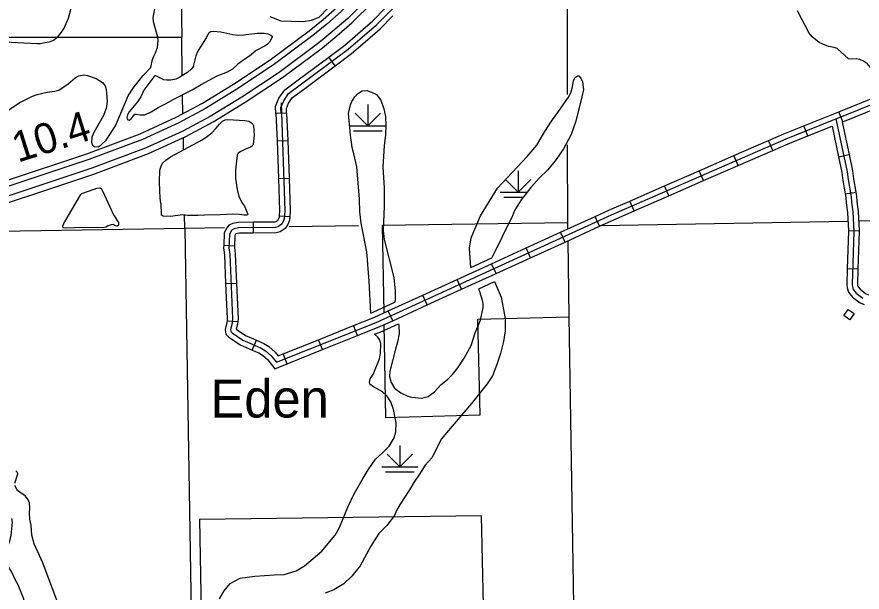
# Model space of a CAD drawing. Extents: x 1084508 to 1142749, y 1057638 to 1093403.
# Drawn here: x 1093716 to 1097414, y 1070508 to 1073024 of the extents above; entities that cross this region are included whole.
import ezdxf

# ---------------------------------------------------------------- set-up
doc = ezdxf.new("R2010")
doc.units = 0
for name, color, linetype in [('Level 19', 7, 'Continuous'), ('Level 24', 7, 'Continuous'), ('Level 32', 7, 'Continuous'), ('Level 35', 7, 'Continuous'), ('Level 4', 7, 'Continuous'), ('Level 44', 7, 'Continuous'), ('Level 45', 7, 'Continuous'), ('Level 47', 7, 'Continuous'), ('Level 48', 7, 'Continuous'), ('Level 5', 7, 'Continuous'), ('Level 56', 7, 'Continuous'), ('Level 7', 7, 'Continuous')]:
    doc.layers.add(name, color=color, linetype=linetype)

msp = doc.modelspace()

# ---------------------------------------------------------------- linework, layer by layer
at = {"layer": 'Level 19'}
for points in [[(1094824.2, 1072836.3), (1094995.1, 1072963.6), (1095055.5, 1073012.7), (1095117.5, 1073066.5), (1095486.3, 1073431.5), (1096480.2, 1074407.3), (1097000.3, 1074928.2)], [(1097019, 1074909.2), (1096499, 1074388.4), (1095505.1, 1073412.5), (1095135.6, 1073046.9), (1095072.6, 1072992.2), (1095011.5, 1072942.5), (1094839.5, 1072814.5)], [(1097047.6, 1074880.1), (1096527.8, 1074359.4), (1095533.7, 1073383.4), (1095163.4, 1073016.9), (1095098.9, 1072961), (1095036.6, 1072910.3), (1094863, 1072781.1)], [(1094878.4, 1072759.3), (1095052.9, 1072889.2), (1095116.1, 1072940.5), (1095181.5, 1072997.4), (1095552.4, 1073364.4), (1096546.5, 1074340.5), (1097066.3, 1074861.1)], [(1092224.5, 1071828.5), (1094022, 1072425.4), (1094255.5, 1072513), (1094412.9, 1072585.2), (1094527.8, 1072646.8), (1094664.6, 1072730.4), (1094824.2, 1072836.3)], [(1094839.5, 1072814.5), (1094678.9, 1072707.9), (1094541.1, 1072623.6), (1094424.8, 1072561.3), (1094265.8, 1072488.3), (1094030.9, 1072400.2), (1092232.9, 1071803.1)], [(1094863, 1072781.1), (1094700.8, 1072673.4), (1094561.4, 1072588.2), (1094443, 1072524.7), (1094281.4, 1072450.7), (1094044.5, 1072361.7), (1092245.7, 1071764.4)], [(1092254, 1071739), (1094053.4, 1072336.6), (1094291.7, 1072426), (1094454.8, 1072500.8), (1094574.7, 1072565.1), (1094715.2, 1072650.9), (1094878.4, 1072759.3)]]:
    msp.add_lwpolyline(points, dxfattribs=at)
at = {"layer": 'Level 32'}
for p, q in [((1097329.7, 1072565.5), (1097312.2, 1072609.2)), ((1097175.9, 1072503.8), (1097158.4, 1072547.5)), ((1094854.3, 1072482.3), (1094901.4, 1072483.9)), ((1097023.6, 1072440.3), (1097004.7, 1072483.5)), ((1096871.7, 1072374.1), (1096852.8, 1072417.2)), ((1097311, 1072411.7), (1097357, 1072421.6)), ((1096719.8, 1072307.8), (1096700.9, 1072350.9)), ((1094860.1, 1072316.7), (1094907.2, 1072318.3)), ((1096567.9, 1072241.5), (1096549, 1072284.7)), ((1097339.6, 1072249.5), (1097386, 1072257.6)), ((1096416, 1072175.2), (1096397.1, 1072218.4)), ((1094863.5, 1072153.5), (1094910.5, 1072150.3)), ((1096264.9, 1072108.1), (1096245.4, 1072150.9)), ((1094749.9, 1072125.6), (1094750.5, 1072078.5)), ((1096114.1, 1072039.3), (1096094.6, 1072082.1)), ((1097353.8, 1072087.6), (1097400.8, 1072089.7)), ((1094621.1, 1072025.3), (1094668.1, 1072023)), ((1095963.3, 1071970.5), (1095943.8, 1072013.3)), ((1095812.6, 1071901.7), (1095793, 1071944.5)), ((1097348.6, 1071923.8), (1097395.6, 1071922.3)), ((1094629.6, 1071857.7), (1094676.7, 1071859.8)), ((1095661.8, 1071832.9), (1095642.2, 1071875.7)), ((1095511, 1071764.1), (1095491.5, 1071806.9)), ((1095360.2, 1071695.3), (1095340.7, 1071738.1)), ((1094635.8, 1071695.2), (1094682.7, 1071691.3)), ((1095206.7, 1071630.2), (1095189.1, 1071673.9)), ((1094745.8, 1071566.9), (1094765, 1071609.9)), ((1095052.8, 1071568.6), (1095035.3, 1071612.3)), ((1094899, 1071506.9), (1094881.5, 1071550.7))]:
    msp.add_line(p, q, dxfattribs=at)
for points in [[(1097081, 1072491.1), (1098396, 1073018.9)], [(1097312.2, 1072609.2), (1097466, 1072671)], [(1094872, 1072648.7), (1094888.6, 1072176.2), (1094886.2, 1072140.6), (1094880.2, 1072126.8), (1094873.4, 1072115.8), (1094858.4, 1072106.1), (1094847.6, 1072103.2), (1094686.5, 1072101.3), (1094667.5, 1072097.4), (1094657.7, 1072093.2), (1094653.2, 1072087.7), (1094646.9, 1072072.4), (1094644.1, 1072014.4), (1094647.4, 1071984.6), (1094660.2, 1071704.3), (1094658.4, 1071683.8), (1094651.3, 1071656.5), (1094652.9, 1071647.7), (1094657.5, 1071642.9), (1094705.2, 1071610.5), (1094742.1, 1071594.3), (1094785.5, 1071575), (1094804.5, 1071563.4), (1094829.4, 1071541.8), (1094851.8, 1071513.4), (1095287.7, 1071688.1), (1096317.9, 1072158.1), (1097081, 1072491.1)], [(1094848.5, 1072601.5), (1094854.3, 1072482.3)], [(1094895.6, 1072602.2), (1094901.4, 1072483.9)], [(1097158.4, 1072547.5), (1097312.2, 1072609.2)], [(1097329.7, 1072565.5), (1097483.5, 1072627.3)], [(1097299.3, 1072578.7), (1097349, 1072346.8), (1097352.6, 1072312.1), (1097365.8, 1072236.3), (1097367.5, 1072213.4), (1097373.7, 1072171.2), (1097377.4, 1072085.9), (1097369.8, 1071854.3), (1097371.1, 1071844), (1097375.3, 1071831.9), (1097388, 1071815.7), (1097417, 1071794.1)], [(1097326.4, 1072564.2), (1097329.7, 1072565.5)], [(1097326.4, 1072564.2), (1097357, 1072421.6)], [(1097004.7, 1072483.5), (1097071.9, 1072512.8), (1097158.4, 1072547.5)], [(1097175.9, 1072503.8), (1097282.1, 1072546.4)], [(1097282.1, 1072546.4), (1097311, 1072411.7)], [(1094901.4, 1072483.9), (1094907.2, 1072318.3)], [(1096852.8, 1072417.2), (1097004.7, 1072483.5)], [(1097023.6, 1072440.3), (1097090.1, 1072469.4), (1097175.9, 1072503.8)], [(1094854.3, 1072482.3), (1094860.1, 1072316.7)], [(1096700.9, 1072350.9), (1096852.8, 1072417.2)], [(1096871.7, 1072374.1), (1097023.6, 1072440.3)], [(1097311, 1072411.7), (1097325.7, 1072343.1), (1097329.3, 1072308.8), (1097339.6, 1072249.5)], [(1097357, 1072421.6), (1097372.2, 1072350.5), (1097376, 1072315.4), (1097386, 1072257.6)], [(1096719.8, 1072307.8), (1096871.7, 1072374.1)], [(1096549, 1072284.7), (1096700.9, 1072350.9)], [(1094860.1, 1072316.7), (1094865.1, 1072176.6), (1094863.5, 1072153.5)], [(1094907.2, 1072318.3), (1094912.2, 1072175.8), (1094910.5, 1072150.3)], [(1096567.9, 1072241.5), (1096719.8, 1072307.8)], [(1096397.1, 1072218.4), (1096549, 1072284.7)], [(1096416, 1072175.2), (1096567.9, 1072241.5)], [(1097339.6, 1072249.5), (1097342.4, 1072233.4), (1097344.1, 1072210.8), (1097350.2, 1072169), (1097353.8, 1072087.6)], [(1097386, 1072257.6), (1097389.2, 1072239.2), (1097391, 1072216), (1097397.1, 1072173.4), (1097400.8, 1072089.7)], [(1096245.4, 1072150.9), (1096308.3, 1072179.6), (1096397.1, 1072218.4)], [(1094863.5, 1072153.5), (1094863, 1072146.3), (1094859.3, 1072137.8), (1094856.2, 1072132.7), (1094848.7, 1072127.9), (1094844.3, 1072126.7), (1094749.9, 1072125.6)], [(1094910.5, 1072150.3), (1094909.5, 1072134.9), (1094901.1, 1072115.8), (1094890.6, 1072099), (1094868.1, 1072084.4), (1094850.8, 1072079.7), (1094750.5, 1072078.5)], [(1096094.6, 1072082.1), (1096245.4, 1072150.9)], [(1096264.9, 1072108.1), (1096327.5, 1072136.6), (1096416, 1072175.2)], [(1094749.9, 1072125.6), (1094684, 1072124.8), (1094660.5, 1072120), (1094643.1, 1072112.6), (1094632.7, 1072099.9), (1094623.6, 1072077.5), (1094621.1, 1072025.3)], [(1094750.5, 1072078.5), (1094689, 1072077.8), (1094674.5, 1072074.8), (1094673.1, 1072074.2), (1094670.2, 1072067.2), (1094668.1, 1072023)], [(1095943.8, 1072013.3), (1096094.6, 1072082.1)], [(1096114.1, 1072039.3), (1096264.9, 1072108.1)], [(1097353.8, 1072087.6), (1097353.9, 1072085.8), (1097348.6, 1071923.8)], [(1097400.8, 1072089.7), (1097401, 1072086.1), (1097395.6, 1071922.3)], [(1095963.3, 1071970.5), (1096114.1, 1072039.3)], [(1094621.1, 1072025.3), (1094620.5, 1072013.6), (1094624, 1071982.8), (1094629.6, 1071857.7)], [(1094668.1, 1072023), (1094667.7, 1072015.1), (1094670.9, 1071986.5), (1094676.7, 1071859.8)], [(1095793, 1071944.5), (1095943.8, 1072013.3)], [(1095812.6, 1071901.7), (1095963.3, 1071970.5)], [(1095642.2, 1071875.7), (1095793, 1071944.5)], [(1095661.8, 1071832.9), (1095812.6, 1071901.7)], [(1097348.6, 1071923.8), (1097346.2, 1071853.2), (1097348, 1071838.6), (1097354.3, 1071820.4), (1097371.5, 1071798.7), (1097404.9, 1071773.7), (1097422.5, 1071765.5)], [(1097395.6, 1071922.3), (1097393.4, 1071855.4), (1097394.2, 1071849.3), (1097396.2, 1071843.3), (1097404.6, 1071832.7), (1097429.1, 1071814.4), (1097442.3, 1071808.2)], [(1094629.6, 1071857.7), (1094636.6, 1071704.8), (1094635.8, 1071695.2)], [(1094676.7, 1071859.8), (1094683.7, 1071703.9), (1094682.7, 1071691.3)], [(1095491.5, 1071806.9), (1095642.2, 1071875.7)], [(1095511, 1071764.1), (1095661.8, 1071832.9)], [(1095340.7, 1071738.1), (1095491.5, 1071806.9)], [(1095360.2, 1071695.3), (1095511, 1071764.1)], [(1095189.1, 1071673.9), (1095278.4, 1071709.7), (1095340.7, 1071738.1)], [(1094635.8, 1071695.2), (1094635.1, 1071687.8), (1094627.3, 1071657.4), (1094631, 1071636.7), (1094642.1, 1071624.9), (1094693.7, 1071589.8), (1094732.6, 1071572.8), (1094745.8, 1071566.9)], [(1094682.7, 1071691.3), (1094681.7, 1071679.8), (1094676.2, 1071658.6), (1094716.6, 1071631.2), (1094751.7, 1071615.9), (1094765, 1071609.9)], [(1095035.3, 1071612.3), (1095189.1, 1071673.9)], [(1095206.7, 1071630.2), (1095297, 1071666.4), (1095360.2, 1071695.3)], [(1094765, 1071609.9), (1094796.5, 1071595.9), (1094818.4, 1071582.5), (1094846.5, 1071558.1), (1094859.4, 1071541.8), (1094881.5, 1071550.7)], [(1094881.5, 1071550.7), (1095035.3, 1071612.3)], [(1095052.8, 1071568.6), (1095206.7, 1071630.2)], [(1094745.8, 1071566.9), (1094774.6, 1071554.1), (1094790.5, 1071544.4), (1094812.3, 1071525.5), (1094844.3, 1071485), (1094899, 1071506.9)], [(1094899, 1071506.9), (1095052.8, 1071568.6)]]:
    msp.add_lwpolyline(points, dxfattribs=at)
at = {"layer": 'Level 35'}
for points in [[(1093604.7, 1072917.1), (1093803, 1072907.1), (1093818.7, 1072907.7), (1093863, 1072915.9), (1093876.2, 1072922.4), (1093894.8, 1072937.1), (1093909, 1072952.2), (1093923.7, 1072974.6), (1093942, 1073018.2), (1093969, 1073117)], [(1097226.2, 1072912.2), (1097194.7, 1072936.4), (1097182.7, 1072952.2), (1097131.7, 1073050)], [(1094488.4, 1072807.6), (1094500.9, 1072853.7), (1094506.8, 1072870.4), (1094543.4, 1072928.7), (1094557.3, 1072955.7), (1094564.7, 1072960.1), (1094574.4, 1072960.8), (1094607.9, 1072958.1), (1094661.1, 1072947.5), (1094685.8, 1072944.7), (1094708.1, 1072945.3), (1094767.2, 1072953.5), (1094797.4, 1072953.2), (1094814.5, 1072949.8), (1094823.8, 1072945.4), (1094832.6, 1072939.5), (1094833.4, 1072935.4), (1094821.1, 1072913.2), (1094813, 1072904.6), (1094802.9, 1072897.6), (1094763.8, 1072877.1), (1094733.4, 1072851.8), (1094712.9, 1072838.7), (1094682.7, 1072816.5)], [(1097532.1, 1072697.5), (1097501.6, 1072718.1), (1097485.7, 1072734.5), (1097472.4, 1072755.1), (1097450.4, 1072803), (1097436.7, 1072818.9), (1097420.4, 1072829.9), (1097403.2, 1072837.2), (1097388.3, 1072840.8), (1097368.3, 1072838.5), (1097354.4, 1072840.9), (1097304.9, 1072886), (1097291.9, 1072889.9), (1097266, 1072894.1), (1097242.5, 1072904.2), (1097226.2, 1072912.2)], [(1094488.4, 1072807.6), (1094479, 1072795.4), (1094464.1, 1072782.6), (1094429.1, 1072760.1), (1094412.4, 1072752.3), (1094389.7, 1072747.8), (1094372.8, 1072747.2), (1094359.6, 1072749.3), (1094347.2, 1072754.3), (1094338.6, 1072759.6), (1094324.2, 1072766.4), (1094320.5, 1072765.7), (1094315.3, 1072761.1), (1094272.1, 1072703.1), (1094258.9, 1072674.3), (1094244.5, 1072652.5), (1094207.7, 1072608.8), (1094200.9, 1072595.7), (1094197.2, 1072584.6), (1094198.1, 1072577.4), (1094201.9, 1072574.4), (1094207.6, 1072572.7), (1094216.8, 1072578), (1094229.7, 1072596), (1094233.7, 1072598.4), (1094239.4, 1072599.2), (1094255.1, 1072595.9), (1094275.5, 1072595), (1094303.9, 1072608.5), (1094334, 1072627.7), (1094367, 1072643.3), (1094400.2, 1072663.2), (1094483.2, 1072705.3), (1094522.2, 1072728.6), (1094593.1, 1072766.7), (1094637.4, 1072783.9), (1094660.8, 1072796.9), (1094682.7, 1072816.5)], [(1094345.6, 1072208.7), (1094343.3, 1072231.2), (1094340.7, 1072301), (1094341.5, 1072354.1), (1094347, 1072371), (1094353.7, 1072384.1), (1094368, 1072397.8), (1094387.9, 1072411.9), (1094526.9, 1072486.6), (1094550.8, 1072502.5), (1094569.1, 1072517.2), (1094587.3, 1072536.1), (1094602.7, 1072555.1), (1094615.2, 1072567.2), (1094627.8, 1072573.9), (1094639.7, 1072575.2), (1094712.8, 1072571), (1094730.5, 1072567.5), (1094742.3, 1072561.3), (1094748.8, 1072554.9), (1094752.1, 1072546.8), (1094754.4, 1072507.3), (1094750.6, 1072467.5), (1094745.6, 1072459.2), (1094738.2, 1072453.6), (1094713.8, 1072444.3), (1094696.5, 1072435.6), (1094684.2, 1072427.3), (1094680.1, 1072419.9), (1094673.4, 1072355.3), (1094672.1, 1072317.2), (1094679.6, 1072269), (1094686.8, 1072238.1), (1094702.8, 1072208.4), (1094712, 1072196.5), (1094726.1, 1072161.1)], [(1093991.4, 1072240.5), (1093996.2, 1072247.9), (1094001.1, 1072251.8), (1094054.3, 1072271.1), (1094065.8, 1072275), (1094079.6, 1072276.4), (1094085, 1072273.1), (1094090.6, 1072263.8), (1094139.1, 1072158.5), (1094160.2, 1072125.3), (1094160.6, 1072113.3), (1094154.8, 1072108.4), (1094146.6, 1072110.4), (1094137, 1072115.7), (1094128.3, 1072115.1), (1094113.4, 1072109), (1094106.1, 1072104), (1094092.4, 1072102), (1094009.9, 1072103.4), (1093927, 1072099.4), (1093920.6, 1072101.7), (1093916.8, 1072105), (1093916.9, 1072110.4), (1093921.6, 1072120.6)], [(1093921.6, 1072120.6), (1093991.4, 1072240.5)], [(1094345.6, 1072208.7), (1094347.5, 1072158.1)], [(1094726.1, 1072161.1), (1094725.3, 1072158.9), (1094721, 1072156.6), (1094710.4, 1072156.2), (1094689.6, 1072159.9), (1094661, 1072161.2), (1094606.3, 1072157.8), (1094536.7, 1072157.4), (1094508.6, 1072155.6), (1094463.8, 1072155.4), (1094440.2, 1072158.4), (1094388.7, 1072150.7), (1094356.7, 1072152.2), (1094348.4, 1072156.6), (1094347.5, 1072158.1)], [(1093882.6, 1070173.3), (1093855.7, 1070200.1), (1093834.3, 1070234), (1093808.9, 1070282.9), (1093795.1, 1070312.3), (1093764.7, 1070399.9), (1093754.1, 1070447.7), (1093744.9, 1070481.4), (1093721.3, 1070540.3), (1093710, 1070560.4), (1093694.2, 1070595.7), (1093676.6, 1070625.3), (1093669.4, 1070646.5), (1093666.6, 1070664.3), (1093668.4, 1070685.1), (1093673.2, 1070701.3), (1093684.3, 1070728.7), (1093691.8, 1070756), (1093697.5, 1070814.4), (1093694.2, 1070830)]]:
    msp.add_lwpolyline(points, dxfattribs=at)
at = {"layer": 'Level 4'}
for points in [[(1096125, 1072684.4), (1096122.9, 1073763)], [(1096126, 1072123.5), (1096125.4, 1072463.9)], [(1096181.8, 1068846.7), (1096153.4, 1070453), (1096132.8, 1071712.6)]]:
    msp.add_lwpolyline(points, dxfattribs=at)
at = {"layer": 'Level 44'}
for p, q in [((1095251, 1072641.1), (1095251, 1072546.9)), ((1095251, 1072546.9), (1095195.5, 1072602.4)), ((1095251, 1072546.9), (1095306.4, 1072602.4)), ((1095172.5, 1072546.9), (1095329.4, 1072546.9)), ((1095188.2, 1072525.5), (1095313.7, 1072525.5)), ((1095909.5, 1072351.1), (1095909.5, 1072256.9)), ((1095909.5, 1072256.9), (1095854, 1072312.4)), ((1095909.5, 1072256.9), (1095965, 1072312.4)), ((1095831.1, 1072256.9), (1095947.7, 1072256.9)), ((1095846.8, 1072235.6), (1095930.7, 1072235.6)), ((1095391.3, 1071150), (1095391.3, 1071055.9)), ((1095391.3, 1071055.9), (1095335.8, 1071111.4)), ((1095391.3, 1071055.9), (1095446.8, 1071111.4)), ((1095312.8, 1071055.9), (1095469.8, 1071055.9)), ((1095328.5, 1071034.5), (1095454.1, 1071034.5))]:
    msp.add_line(p, q, dxfattribs=at)
at = {"layer": 'Level 45'}
for p, q in [((1095108.4, 1072810.2), (1095080.3, 1072847.9)), ((1094895.6, 1072602.2), (1094848.5, 1072601.5))]:
    msp.add_line(p, q, dxfattribs=at)
for points in [[(1094872, 1072601.8), (1094871.6, 1072628.2), (1094883.4, 1072657.5), (1094905.2, 1072688.2), (1095165.8, 1072882.2), (1095289, 1072989), (1095408.9, 1073110.3), (1096240.7, 1073920.5)], [(1095208.3, 1072950.2), (1095272.9, 1073006.2), (1095328.1, 1073062)], [(1095239.2, 1072914.7), (1095305.1, 1072971.8), (1095361.6, 1073028.9)], [(1095080.3, 1072847.9), (1095151, 1072900.6), (1095208.3, 1072950.2)], [(1095108.4, 1072810.2), (1095180.5, 1072863.8), (1095239.2, 1072914.7)], [(1094947.4, 1072749), (1095080.3, 1072847.9)], [(1094975.5, 1072711.2), (1095108.4, 1072810.2)], [(1094848.5, 1072601.5), (1094848, 1072632.6), (1094862.6, 1072668.8), (1094888.1, 1072704.8), (1094947.4, 1072749)], [(1094895.6, 1072602.2), (1094895.3, 1072623.8), (1094904.3, 1072646.1), (1094922.2, 1072671.5), (1094975.5, 1072711.2)]]:
    msp.add_lwpolyline(points, dxfattribs=at)
at = {"layer": 'Level 47'}
for points in [[(1094302.1, 1072802.8), (1094309.1, 1072837.8), (1094314.8, 1072851.9), (1094323.3, 1072867.1), (1094332.1, 1072890.5), (1094334.6, 1072920.5), (1094333, 1072935.6), (1094314.7, 1073002.9), (1094312.4, 1073021.1), (1094322.1, 1073074.5)], [(1094823, 1073026.1), (1094871.2, 1073007.3), (1094918.2, 1073004.6), (1094969.2, 1073004.5), (1095004.8, 1073009.5), (1095039.1, 1073023.2), (1095078.3, 1073063.3)], [(1093648.7, 1072596.2), (1093726.4, 1072647.5), (1093784.7, 1072676.7), (1093804.8, 1072684.3), (1093849.3, 1072694.2), (1093882.4, 1072698.5), (1093899.4, 1072704.1), (1093940.2, 1072730.9), (1093971, 1072757.7), (1093988, 1072766.7), (1094008.9, 1072770.5), (1094024.9, 1072767.3), (1094063.6, 1072755), (1094091.1, 1072736.8), (1094103.2, 1072722.4), (1094107.1, 1072705.8), (1094111.9, 1072655.7), (1094107, 1072623.1), (1094093.6, 1072589.4), (1094052.4, 1072518.2), (1094043.6, 1072497.8), (1094042.1, 1072475.8), (1094046.6, 1072462.7), (1094055.3, 1072456.4), (1094071.3, 1072456), (1094085.4, 1072464), (1094106.4, 1072484.8), (1094147.9, 1072548.1), (1094202.6, 1072679.4), (1094225.1, 1072712.5), (1094266.9, 1072765.5), (1094302.1, 1072802.8)], [(1095702.3, 1071927.7), (1095696.2, 1072013), (1095703.3, 1072057.9), (1095743.7, 1072153.9), (1095818.8, 1072274.6), (1095947.9, 1072413.4), (1095991.4, 1072463.2), (1096026.1, 1072522.8), (1096055.7, 1072568.1), (1096083.3, 1072605.2), (1096132.1, 1072676.6), (1096140.9, 1072695.7), (1096147.1, 1072718.3), (1096151.6, 1072745.1), (1096158.3, 1072758.3), (1096168.1, 1072766.4), (1096174.1, 1072765.7), (1096182.9, 1072755.9), (1096190.3, 1072739.8), (1096194.8, 1072706.9), (1096188.3, 1072674.3), (1096161.6, 1072567.5), (1096141.6, 1072509.9), (1096106.9, 1072446.2), (1096075.5, 1072399.6), (1096038.4, 1072355), (1096001, 1072318.9), (1095964.4, 1072278.1), (1095921.7, 1072224.2), (1095893.4, 1072177.3), (1095884.4, 1072154.1), (1095794.4, 1071969.7)], [(1095264.6, 1071728.7), (1095258.1, 1071867.6), (1095246.7, 1071997), (1095221.7, 1072121.7), (1095217, 1072171.2), (1095214.9, 1072226.5), (1095203.5, 1072368.2), (1095190.7, 1072425.7), (1095182.9, 1072453.1), (1095175.6, 1072506), (1095167.5, 1072601.6), (1095175.7, 1072639), (1095182.1, 1072654.6), (1095194.9, 1072674.8), (1095206.1, 1072687.4), (1095226.3, 1072701), (1095247, 1072702), (1095267.9, 1072695.4), (1095288.9, 1072684.2), (1095308.5, 1072660.3), (1095322, 1072621.4), (1095328.4, 1072588.3), (1095330.5, 1072550.7), (1095328.8, 1072507.2), (1095323.7, 1072460.8), (1095317, 1072366.3), (1095323.7, 1072275.9), (1095323.7, 1072196.4), (1095319.3, 1072090.3), (1095322.7, 1072050.8), (1095366, 1071884.6), (1095371.4, 1071824.4), (1095371.6, 1071789.2), (1095370.3, 1071776.2)], [(1095702.3, 1071927.7), (1095794.4, 1071969.7)], [(1095806.1, 1071866.8), (1095834.7, 1071798.4), (1095852.5, 1071704.3), (1095852.3, 1071651.5), (1095845.4, 1071604.4), (1095831.4, 1071552.1), (1095815.4, 1071503.2), (1095796.6, 1071453.5), (1095773.6, 1071419.7), (1095704.6, 1071333.2), (1095595, 1071204.2), (1095574.5, 1071178.3), (1095551.4, 1071137), (1095532.6, 1071097.7), (1095502, 1071063.4), (1095478.2, 1071023.9), (1095452.8, 1070987.9), (1095433.8, 1070954.9), (1095392.5, 1070892.8), (1095376.8, 1070865), (1095368.1, 1070843.9), (1095335, 1070800.1), (1095299.5, 1070764), (1095264.3, 1070709.4), (1095218.5, 1070623.3), (1095181.4, 1070577.5), (1095146.1, 1070544.2), (1095102.5, 1070518), (1095065.3, 1070503.6)], [(1095736.5, 1071835.1), (1095806.1, 1071866.8)], [(1095621.5, 1071460), (1095644.8, 1071488.8), (1095673.1, 1071531.8), (1095703, 1071586.3), (1095721.6, 1071642.8), (1095744.9, 1071697.1), (1095756.3, 1071753.4), (1095755.4, 1071771), (1095752, 1071789.4), (1095736.5, 1071835.1)], [(1095264.6, 1071728.7), (1095278, 1071734.1), (1095370.3, 1071776.2)], [(1095281.3, 1071635.8), (1095306, 1071645.7), (1095385.7, 1071682.1)], [(1095385.7, 1071682.1), (1095387.8, 1071674), (1095388.9, 1071639.8), (1095381.6, 1071602.1), (1095372.6, 1071571.3), (1095347.8, 1071474.3), (1095346.7, 1071450.7), (1095353.2, 1071424.5), (1095368.7, 1071399.9), (1095396, 1071380), (1095426.5, 1071365.9), (1095444.2, 1071361.1), (1095485.7, 1071356.8), (1095515.9, 1071363.8), (1095543.4, 1071384.5), (1095572.8, 1071416.6), (1095600.6, 1071438.6), (1095621.5, 1071460)], [(1095226.7, 1071000), (1095252.9, 1071043.3), (1095285, 1071089.3), (1095316.9, 1071119), (1095344.5, 1071147.2), (1095366.9, 1071183.5), (1095373.9, 1071209.5), (1095375.7, 1071249.2), (1095364.5, 1071306.6), (1095352.5, 1071339.9), (1095334, 1071367.3), (1095316, 1071383.7), (1095276.7, 1071406), (1095261, 1071417.4), (1095259.4, 1071426.1), (1095261.5, 1071441), (1095274.7, 1071459.3), (1095303.2, 1071528.5), (1095307.1, 1071551.6), (1095307.9, 1071595), (1095302.6, 1071612.8), (1095294.8, 1071623.8), (1095281.3, 1071635.8)], [(1093706.8, 1070984.8), (1093720.2, 1071025.4), (1093719, 1071031.7), (1093711.3, 1071038)], [(1093900.8, 1070445.9), (1093830.4, 1070636.3), (1093792.7, 1070719.4), (1093781.4, 1070756.7), (1093778.8, 1070800.7), (1093773.6, 1070826.9), (1093771.5, 1070853.3), (1093772.9, 1070877.2), (1093771, 1070898.2), (1093765.5, 1070911.9), (1093753.4, 1070928.4), (1093719.4, 1070953.1), (1093707.7, 1070974.1)], [(1094602.6, 1070479), (1094622.8, 1070514.2), (1094649.4, 1070545.3), (1094692.8, 1070569.6), (1094757.4, 1070577.4), (1094841.8, 1070584.3), (1094886.3, 1070584.8), (1094938.1, 1070601.6), (1094974, 1070623.2), (1095049.7, 1070687.6), (1095086, 1070729.4), (1095108.2, 1070757.4), (1095127.9, 1070790.5), (1095163.6, 1070879.4), (1095192.4, 1070938.2), (1095226.7, 1071000)]]:
    msp.add_lwpolyline(points, dxfattribs=at)
at = {"layer": 'Level 5'}
for points in [[(1094440, 1072770.9), (1094437.4, 1072935.1)], [(1094442.8, 1072601.2), (1094441.5, 1072679.1)], [(1094445.3, 1072446.1), (1094444.5, 1072496.1)], [(1094451, 1072098.9), (1094450, 1072157.1)], [(1097352, 1072129.1), (1096268.7, 1072109.8)], [(1097893, 1072138.7), (1097399.1, 1072129.9)], [(1094624.7, 1072101.5), (1094451, 1072098.9), (1093280.9, 1072080)], [(1094451, 1072098.9), (1094478.5, 1070419.9), (1094480, 1070334.9)], [(1095210.8, 1072110.1), (1094907.5, 1072105.6)]]:
    msp.add_lwpolyline(points, dxfattribs=at)
at = {"layer": 'Level 56'}
msp.add_lwpolyline([(1097379.2, 1071726.1), (1097360.7, 1071699.2), (1097333.7, 1071717.7), (1097352.2, 1071744.6)], close=True, dxfattribs=at)
at = {"layer": 'Level 7'}
for points in [[(1093599, 1073763), (1094423.9, 1073765.6), (1094437.4, 1072935.1)], [(1093613, 1072272.6), (1093606.8, 1072935.1), (1094437.4, 1072935.1)], [(1096126, 1072123.5), (1095314.8, 1072111.6)], [(1096126.5, 1072096.7), (1096126, 1072123.5)], [(1095314.8, 1072111.6), (1095321.4, 1071729.3)], [(1096132.8, 1071712.6), (1096127.3, 1072045.3)], [(1095322.2, 1071678), (1095329.2, 1071272.5), (1095742.6, 1071282.9), (1095732.2, 1071702), (1096132.8, 1071712.6)], [(1095757.5, 1070451.8), (1095749.2, 1070842.6), (1094515.7, 1070825.8), (1094522.5, 1070421)]]:
    msp.add_lwpolyline(points, dxfattribs=at)

# ---------------------------------------------------------------- texts
at = {"layer": 'Level 24'}
msp.add_text('Eden', height=165.73, dxfattribs=at).set_placement((1094563.2, 1071271.8))
at = {"layer": 'Level 48'}
msp.add_text('10.4', height=132.58, rotation=17.5064, dxfattribs=at).set_placement((1093720.4, 1072385.9))

doc.saveas('drawing.dxf')
